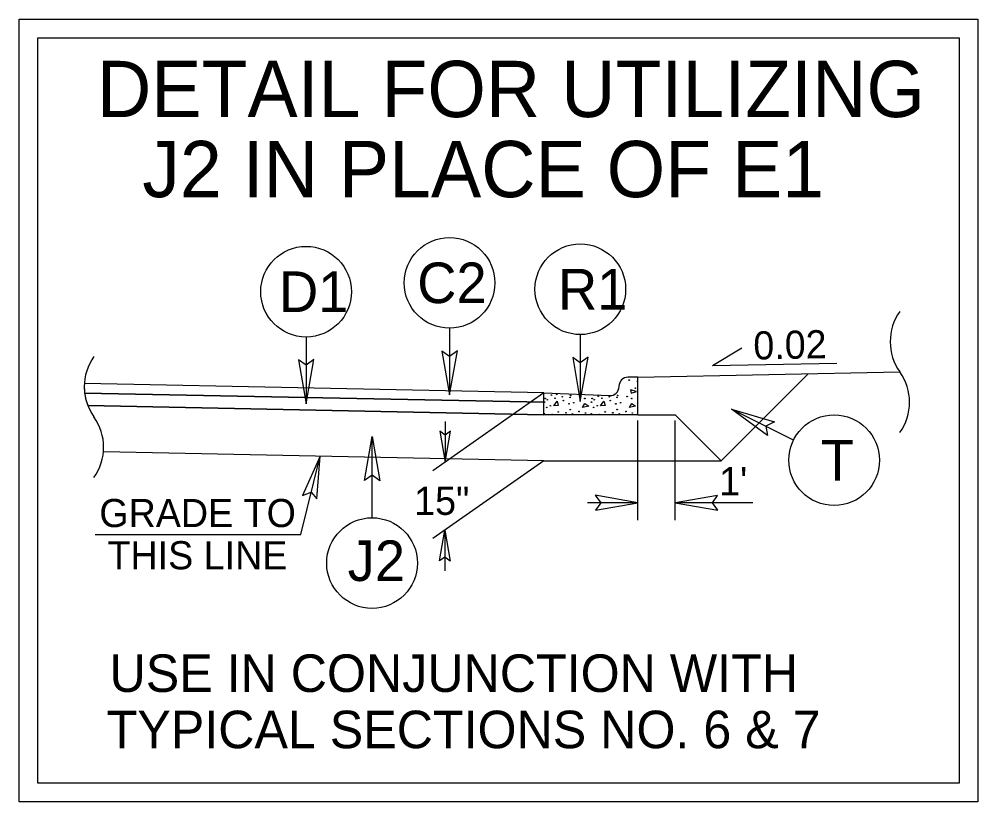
# Model space of a CAD drawing. Extents: x 1487909 to 1489267, y 497866 to 499814.
# Drawn here: x 1489069.13 to 1489094.67, y 498128.44 to 498149.3 of the extents above; entities that cross this region are included whole.
import ezdxf

# ---------------------------------------------------------------- set-up
doc = ezdxf.new("R2010")
doc.units = 0
for name, color, linetype in [('Default', 7, 'Continuous'), ('Old_Level_10', 7, 'Continuous'), ('Prop Dimension', 7, 'Continuous'), ('Prop Dimension Text', 7, 'Continuous'), ('Prop Shade Light', 7, 'Continuous'), ('Prop Terminator CELL', 7, 'Continuous'), ('Sheet Typical CELL', 7, 'Continuous'), ('Typical Curb CELL', 7, 'Continuous'), ('Typical Detail Wedge2 CELL', 7, 'Continuous'), ('Typical ID Circle CELL', 7, 'Continuous'), ('Typical Pavement Slope CELL', 7, 'Continuous'), ('Typical Pavement Slope Information CELL', 7, 'Continuous'), ('Typical Terminator CELL', 7, 'Continuous'), ('Typical Text ID Circle CELL', 7, 'Continuous'), ('Typical Text Label CELL', 7, 'Continuous')]:
    doc.layers.add(name, color=color, linetype=linetype)

msp = doc.modelspace()

# ---------------------------------------------------------------- linework, layer by layer
at = {"layer": 'Old_Level_10'}
for p, q in [((1489083.112, 498139.092), (1489070.87, 498139.336)), ((1489083.112, 498138.758), (1489083.112, 498139.092)), ((1489070.955, 498139.002), (1489083.112, 498138.758))]:
    msp.add_line(p, q, dxfattribs=at)
msp.add_arc((1489072.251, 498139.507), 1.391, 187.0449, 201.3099, dxfattribs=at)
at = {"layer": 'Prop Dimension'}
for p, q in [((1489085.612, 498135.952), (1489085.612, 498138.606)), ((1489086.612, 498135.952), (1489086.612, 498138.606)), ((1489076.628, 498135.568), (1489077.144, 498137.651)), ((1489085.612, 498136.412), (1489084.275, 498136.412)), ((1489088.68, 498136.412), (1489086.612, 498136.412)), ((1489071.155, 498135.568), (1489076.628, 498135.568))]:
    msp.add_line(p, q, dxfattribs=at)
for centre, start, end in [((1489093.73, 498140.705), 144.5148, 215.4852), ((1489072.251, 498139.507), 144.5148, 215.4852), ((1489072.251, 498139.507), 144.5148, 215.4852), ((1489091.465, 498139.091), 324.5148, 35.4852), ((1489069.986, 498137.892), 324.5148, 35.4852), ((1489069.986, 498137.892), 324.5148, 35.4852)]:
    msp.add_arc(centre, 1.391, start, end, dxfattribs=at)
at = {"layer": 'Prop Shade Light'}
for p, q in [((1489083.112, 498139.342), (1489070.862, 498139.587)), ((1489070.87, 498139.336), (1489083.112, 498139.092)), ((1489083.112, 498139.092), (1489083.112, 498139.342))]:
    msp.add_line(p, q, dxfattribs=at)
msp.add_arc((1489072.251, 498139.507), 1.391, 176.7203, 187.0449, dxfattribs=at)
at = {"layer": 'Prop Terminator CELL'}
for points in [[(1489077.062, 498136.513), (1489077.144, 498137.651), (1489076.678, 498136.601), (1489076.907, 498136.693)], [(1489084.487, 498136.218), (1489085.612, 498136.412), (1489084.48, 498136.612), (1489084.624, 498136.412)], [(1489087.737, 498136.605), (1489086.612, 498136.412), (1489087.743, 498136.212), (1489087.599, 498136.412)]]:
    msp.add_lwpolyline(points, close=True, dxfattribs=at)
at = {"layer": 'Sheet Typical CELL'}
for points in [[(1489069.125, 498149.302), (1489094.674, 498149.302), (1489094.674, 498128.44), (1489069.125, 498128.44)], [(1489069.625, 498148.802), (1489094.174, 498148.802), (1489094.174, 498128.94), (1489069.625, 498128.94)]]:
    msp.add_lwpolyline(points, close=True, dxfattribs=at)
at = {"layer": 'Typical Curb CELL'}
for p, q in [((1489085.612, 498139.758), (1489085.351, 498139.758)), ((1489085.612, 498138.758), (1489085.612, 498139.758)), ((1489083.112, 498138.758), (1489083.112, 498139.342)), ((1489083.112, 498139.342), (1489084.862, 498139.269)), ((1489085.112, 498139.508), (1489085.112, 498139.519)), ((1489085.421, 498139.425), (1489085.438, 498139.334)), ((1489085.575, 498139.38), (1489085.421, 498139.425)), ((1489085.438, 498139.334), (1489085.575, 498139.38)), ((1489083.372, 498138.998), (1489083.459, 498139.118)), ((1489083.459, 498139.118), (1489083.493, 498139.004)), ((1489084.138, 498138.947), (1489084.2, 498139.061)), ((1489084.2, 498139.061), (1489084.304, 498138.986)), ((1489084.622, 498138.998), (1489084.708, 498139.118)), ((1489084.708, 498139.118), (1489084.742, 498139.004)), ((1489085.387, 498138.947), (1489085.449, 498139.061)), ((1489085.449, 498139.061), (1489085.552, 498138.986)), ((1489083.493, 498139.004), (1489083.372, 498138.998)), ((1489084.304, 498138.986), (1489084.138, 498138.947)), ((1489084.742, 498139.004), (1489084.622, 498138.998)), ((1489085.552, 498138.986), (1489085.387, 498138.947)), ((1489085.612, 498138.758), (1489083.112, 498138.758))]:
    msp.add_line(p, q, dxfattribs=at)
for centre in [(1489085.381, 498139.682), (1489085.598, 498139.648), (1489083.31, 498139.283), (1489083.453, 498139.3), (1489083.824, 498139.271), (1489085.073, 498139.271), (1489085.547, 498139.466), (1489083.129, 498139.095), (1489083.146, 498139.192), (1489083.202, 498139.158), (1489083.407, 498139.198), (1489083.601, 498139.237), (1489083.63, 498139.135), (1489083.778, 498139.05), (1489083.807, 498139.221), (1489083.904, 498139.078), (1489084.081, 498139.243), (1489084.201, 498139.192), (1489084.378, 498139.095), (1489084.395, 498139.192), (1489084.451, 498139.158), (1489084.559, 498139.252), (1489084.656, 498139.198), (1489084.851, 498139.237), (1489084.879, 498139.135), (1489085.027, 498139.05), (1489085.056, 498139.221), (1489085.153, 498139.078), (1489085.33, 498139.243), (1489085.45, 498139.192), (1489083.123, 498138.787), (1489083.186, 498138.953), (1489083.282, 498138.998), (1489083.333, 498138.764), (1489083.493, 498138.833), (1489083.698, 498138.81), (1489083.813, 498138.896), (1489083.87, 498138.781), (1489084.047, 498138.844), (1489084.218, 498138.804), (1489084.372, 498138.787), (1489084.435, 498138.953), (1489084.531, 498138.998), (1489084.582, 498138.764), (1489084.742, 498138.833), (1489084.947, 498138.81), (1489085.062, 498138.896), (1489085.119, 498138.781), (1489085.296, 498138.844), (1489085.467, 498138.804)]:
    msp.add_circle(centre, 0.00802, dxfattribs=at)
for centre, start, end in [((1489085.351, 498139.519), 90, 180), ((1489084.872, 498139.508), 267.6155, 0)]:
    msp.add_arc(centre, 0.24, start, end, dxfattribs=at)
at = {"layer": 'Typical Detail Wedge2 CELL'}
for p, q in [((1489083.112, 498139.342), (1489080.148, 498137.266)), ((1489080.479, 498138.582), (1489080.479, 498137.498)), ((1489083.112, 498137.532), (1489080.148, 498135.457)), ((1489080.469, 498135.681), (1489080.469, 498134.597))]:
    msp.add_line(p, q, dxfattribs=at)
at = {"layer": 'Typical ID Circle CELL'}
for p, q in [((1489080.595, 498141.065), (1489080.595, 498139.285)), ((1489076.772, 498140.83), (1489076.772, 498139.05)), ((1489084.08, 498140.895), (1489084.08, 498139.115)), ((1489089.763, 498138.084), (1489088.106, 498138.908)), ((1489078.53, 498136.012), (1489078.53, 498138.179))]:
    msp.add_line(p, q, dxfattribs=at)
for centre in [(1489080.595, 498142.273), (1489076.772, 498142.038), (1489084.08, 498142.103), (1489090.845, 498137.546), (1489078.53, 498134.804)]:
    msp.add_circle(centre, 1.208, dxfattribs=at)
at = {"layer": 'Typical Pavement Slope CELL'}
for p, q in [((1489085.612, 498139.758), (1489092.597, 498139.898)), ((1489090.155, 498139.849), (1489087.838, 498137.532)), ((1489083.112, 498139.342), (1489070.862, 498139.587)), ((1489083.112, 498139.092), (1489070.87, 498139.336)), ((1489083.112, 498138.758), (1489070.955, 498139.002)), ((1489085.612, 498138.758), (1489086.612, 498138.758)), ((1489086.612, 498138.758), (1489087.838, 498137.532)), ((1489083.112, 498137.532), (1489071.371, 498137.767)), ((1489083.112, 498137.532), (1489087.838, 498137.532))]:
    msp.add_line(p, q, dxfattribs=at)
at = {"layer": 'Typical Pavement Slope Information CELL'}
for q in [(1489088.384, 498140.54), (1489090.917, 498140.133)]:
    msp.add_line((1489087.601, 498140.067), q, dxfattribs=at)
at = {"layer": 'Typical Terminator CELL'}
for points in [[(1489080.393, 498140.457), (1489080.595, 498139.285), (1489080.803, 498140.464), (1489080.595, 498140.314)], [(1489076.57, 498140.222), (1489076.772, 498139.05), (1489076.98, 498140.228), (1489076.772, 498140.079)], [(1489083.878, 498140.287), (1489084.08, 498139.115), (1489084.288, 498140.294), (1489084.08, 498140.144)], [(1489089.065, 498138.206), (1489088.106, 498138.908), (1489089.253, 498138.57), (1489089.026, 498138.45)], [(1489080.338, 498138.318), (1489080.479, 498137.498), (1489080.625, 498138.323), (1489080.479, 498138.218)], [(1489078.328, 498137.007), (1489078.53, 498138.179), (1489078.738, 498137), (1489078.53, 498137.15)], [(1489080.327, 498134.861), (1489080.469, 498135.681), (1489080.614, 498134.857), (1489080.469, 498134.961)]]:
    msp.add_lwpolyline(points, close=True, dxfattribs=at)

# ---------------------------------------------------------------- texts
at = {"layer": 'Default'}
msp.add_text('DETAIL FOR UTILIZING', height=1.5, rotation=359.9999, dxfattribs=at).set_placement((1489071.198, 498146.692))
at = {"layer": 'Prop Dimension Text'}
for s, p in [("1'", (1489087.78, 498136.611)), ('15"', (1489079.652, 498136.088)), ('GRADE TO', (1489071.262, 498135.763)), ('THIS LINE', (1489071.48, 498134.638))]:
    msp.add_text(s, height=0.75, dxfattribs=at).set_placement(p)
at = {"layer": 'Typical Pavement Slope Information CELL'}
msp.add_text('0.02', height=0.75, rotation=1.1457, dxfattribs=at).set_placement((1489088.699, 498140.228))
at = {"layer": 'Typical Text ID Circle CELL'}
for s, height, p in [('C2', 1.0817, (1489079.735, 498141.733)), ('R1', 1.0817, (1489083.486, 498141.563)), ('D1', 1.0817, (1489076.051, 498141.497)), ('T', 1.082, (1489090.489, 498137.005)), ('J2', 1.0817, (1489077.881, 498134.326))]:
    msp.add_text(s, height=height, dxfattribs=at).set_placement(p)
at = {"layer": 'Typical Text Label CELL'}
msp.add_text('J2 IN PLACE OF E1', height=1.5, rotation=360, dxfattribs=at).set_placement((1489072.408, 498144.557))
for s, p in [('USE IN CONJUNCTION WITH ', (1489071.533, 498131.369)), ('TYPICAL SECTIONS NO. 6 & 7', (1489071.458, 498129.869))]:
    msp.add_text(s, height=1, dxfattribs=at).set_placement(p)

doc.saveas('drawing.dxf')
